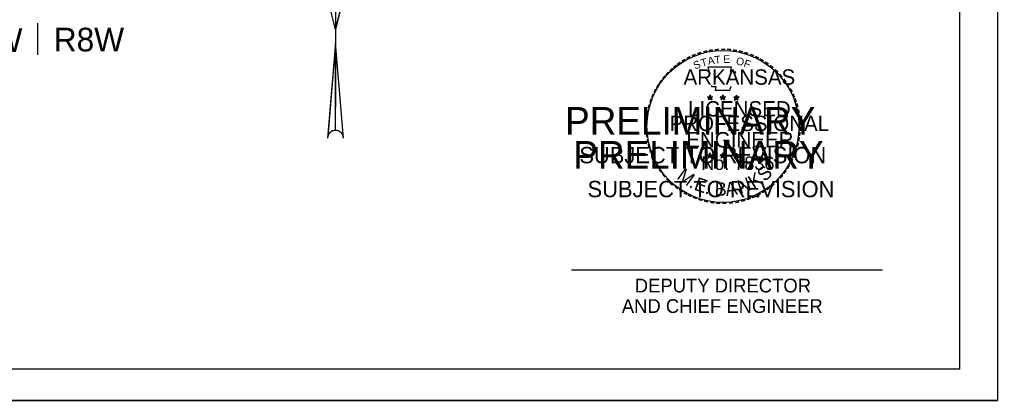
# Model space of a CAD drawing. Extents: x 1367863 to 1368197, y 380048 to 380261.
# Drawn here: x 1368072.7 to 1368196.7, y 380048.1 to 380096.4 of the extents above; entities that cross this region are included whole.
import ezdxf

# ---------------------------------------------------------------- set-up
doc = ezdxf.new("R2010")
doc.units = 0
for name, color, linetype in [('R_Border', 7, 'Continuous'), ('R_Border PE', 7, 'Continuous'), ('R_Border Prem', 7, 'Continuous'), ('R_Draft', 7, 'Continuous'), ('R_No Plot', 7, 'Continuous')]:
    doc.layers.add(name, color=color, linetype=linetype)

msp = doc.modelspace()

# ---------------------------------------------------------------- linework, layer by layer
at = {"layer": 'R_Border'}
for p, q in [((1368191.97, 380052.08), (1368191.97, 380257.54)), ((1368075.06, 380091.94), (1368075.06, 380095.94)), ((1368191.97, 380052.08), (1367875.8, 380052.08))]:
    msp.add_line(p, q, dxfattribs=at)
at = {"layer": 'R_Border PE'}
for p, q in [((1368160.28, 380086.85), (1368160.24, 380086.6)), ((1368160.28, 380086.49), (1368160.28, 380086.85)), ((1368160.28, 380086.85), (1368160.33, 380086.61)), ((1368161.91, 380086.85), (1368161.87, 380086.6)), ((1368161.91, 380086.49), (1368161.91, 380086.85)), ((1368161.91, 380086.85), (1368161.95, 380086.61)), ((1368163.62, 380086.83), (1368163.58, 380086.59)), ((1368163.62, 380086.48), (1368163.62, 380086.83)), ((1368163.62, 380086.83), (1368163.66, 380086.59)), ((1368159.94, 380086.6), (1368160.28, 380086.49)), ((1368159.94, 380086.6), (1368160.19, 380086.56)), ((1368159.94, 380086.6), (1368160.17, 380086.48)), ((1368160.07, 380086.2), (1368160.28, 380086.49)), ((1368160.07, 380086.2), (1368160.19, 380086.44)), ((1368160.07, 380086.2), (1368160.27, 380086.41)), ((1368160.49, 380086.2), (1368160.27, 380086.41)), ((1368160.61, 380086.6), (1368160.28, 380086.49)), ((1368160.49, 380086.2), (1368160.28, 380086.49)), ((1368160.61, 380086.6), (1368160.34, 380086.55)), ((1368160.49, 380086.2), (1368160.35, 380086.48)), ((1368160.61, 380086.6), (1368160.42, 380086.5)), ((1368161.57, 380086.6), (1368161.91, 380086.49)), ((1368161.57, 380086.6), (1368161.81, 380086.56)), ((1368161.57, 380086.6), (1368161.79, 380086.48)), ((1368161.69, 380086.2), (1368161.91, 380086.49)), ((1368161.69, 380086.2), (1368161.82, 380086.44)), ((1368161.69, 380086.2), (1368161.9, 380086.41)), ((1368162.11, 380086.2), (1368161.9, 380086.41)), ((1368162.24, 380086.6), (1368161.91, 380086.49)), ((1368162.11, 380086.2), (1368161.91, 380086.49)), ((1368162.24, 380086.6), (1368161.96, 380086.55)), ((1368162.11, 380086.2), (1368161.97, 380086.48)), ((1368162.24, 380086.6), (1368162.04, 380086.5)), ((1368163.28, 380086.59), (1368163.62, 380086.48)), ((1368163.28, 380086.59), (1368163.52, 380086.54)), ((1368163.28, 380086.59), (1368163.51, 380086.47)), ((1368163.4, 380086.19), (1368163.62, 380086.48)), ((1368163.4, 380086.19), (1368163.53, 380086.43)), ((1368163.4, 380086.19), (1368163.62, 380086.4)), ((1368163.96, 380086.59), (1368163.62, 380086.48)), ((1368163.82, 380086.19), (1368163.62, 380086.48)), ((1368163.82, 380086.19), (1368163.62, 380086.4)), ((1368163.96, 380086.59), (1368163.67, 380086.54)), ((1368163.82, 380086.19), (1368163.69, 380086.47)), ((1368163.96, 380086.59), (1368163.75, 380086.49)), ((1368159.93, 380079.24), (1368160.27, 380079.13)), ((1368159.93, 380079.24), (1368160.19, 380079.19)), ((1368159.93, 380079.24), (1368160.17, 380079.12)), ((1368160.27, 380079.48), (1368160.23, 380079.24)), ((1368160.27, 380079.13), (1368160.27, 380079.48)), ((1368160.27, 380079.48), (1368160.32, 380079.24)), ((1368160.61, 380079.24), (1368160.27, 380079.13)), ((1368160.61, 380079.24), (1368160.33, 380079.19)), ((1368160.61, 380079.24), (1368160.42, 380079.14)), ((1368161.56, 380079.24), (1368161.9, 380079.13)), ((1368161.56, 380079.24), (1368161.81, 380079.19)), ((1368161.56, 380079.24), (1368161.79, 380079.12)), ((1368161.9, 380079.48), (1368161.86, 380079.24)), ((1368161.9, 380079.13), (1368161.9, 380079.48)), ((1368161.9, 380079.48), (1368161.94, 380079.24)), ((1368162.24, 380079.24), (1368161.9, 380079.13)), ((1368162.24, 380079.24), (1368161.95, 380079.19)), ((1368162.24, 380079.24), (1368162.03, 380079.14)), ((1368163.28, 380079.23), (1368163.62, 380079.12)), ((1368163.28, 380079.23), (1368163.52, 380079.18)), ((1368163.28, 380079.23), (1368163.51, 380079.11)), ((1368163.62, 380079.47), (1368163.58, 380079.23)), ((1368163.62, 380079.12), (1368163.62, 380079.47)), ((1368163.62, 380079.47), (1368163.66, 380079.23)), ((1368163.96, 380079.23), (1368163.62, 380079.12)), ((1368163.96, 380079.23), (1368163.67, 380079.18)), ((1368163.96, 380079.23), (1368163.75, 380079.13)), ((1368160.07, 380078.84), (1368160.27, 380079.13)), ((1368160.07, 380078.84), (1368160.19, 380079.08)), ((1368160.07, 380078.84), (1368160.27, 380079.06)), ((1368160.49, 380078.84), (1368160.27, 380079.13)), ((1368160.49, 380078.84), (1368160.27, 380079.05)), ((1368160.49, 380078.84), (1368160.35, 380079.12)), ((1368161.69, 380078.84), (1368161.9, 380079.13)), ((1368161.69, 380078.84), (1368161.81, 380079.08)), ((1368161.69, 380078.84), (1368161.9, 380079.06)), ((1368162.1, 380078.84), (1368161.9, 380079.13)), ((1368162.1, 380078.84), (1368161.9, 380079.05)), ((1368162.1, 380078.84), (1368161.97, 380079.12)), ((1368163.4, 380078.83), (1368163.62, 380079.12)), ((1368163.4, 380078.83), (1368163.53, 380079.07)), ((1368163.4, 380078.83), (1368163.62, 380079.05)), ((1368163.82, 380078.83), (1368163.62, 380079.12)), ((1368163.82, 380078.83), (1368163.62, 380079.04)), ((1368163.82, 380078.83), (1368163.68, 380079.11)), ((1368142.71, 380064.66), (1368182.14, 380064.66))]:
    msp.add_line(p, q, dxfattribs=at)
for points in [[(1368159.98, 380090.37), (1368160.24, 380089.56)], [(1368163.39, 380089.48), (1368163.53, 380089.75), (1368162.87, 380089.73), (1368163, 380090.37), (1368159.98, 380090.37)], [(1368160.46, 380088.02), (1368160.46, 380087.93), (1368161, 380087.91), (1368160.95, 380087.45), (1368162.77, 380087.45), (1368162.97, 380087.97)], [(1368160.28, 380086.85), (1368160.49, 380086.2), (1368159.94, 380086.6), (1368160.61, 380086.6), (1368160.07, 380086.2), (1368160.28, 380086.85)], [(1368161.91, 380086.85), (1368162.11, 380086.2), (1368161.57, 380086.6), (1368162.24, 380086.6), (1368161.69, 380086.2), (1368161.91, 380086.85)], [(1368163.62, 380086.83), (1368163.82, 380086.19), (1368163.28, 380086.59), (1368163.96, 380086.59), (1368163.4, 380086.19), (1368163.62, 380086.83)], [(1368160.27, 380079.48), (1368160.49, 380078.84), (1368159.93, 380079.24), (1368160.61, 380079.24), (1368160.07, 380078.84), (1368160.27, 380079.48)], [(1368161.9, 380079.48), (1368162.1, 380078.84), (1368161.56, 380079.24), (1368162.24, 380079.24), (1368161.69, 380078.84), (1368161.9, 380079.48)], [(1368163.62, 380079.47), (1368163.82, 380078.83), (1368163.28, 380079.23), (1368163.96, 380079.23), (1368163.4, 380078.83), (1368163.62, 380079.47)]]:
    msp.add_lwpolyline(points, dxfattribs=at)
for centre, radius in [((1368161.92, 380082.85), 9.64), ((1368160.27, 380086.48), 0.167), ((1368160.27, 380086.48), 0.141), ((1368160.27, 380086.48), 0.113), ((1368160.27, 380086.48), 0.0963), ((1368160.27, 380086.48), 0.0726), ((1368160.27, 380086.48), 0.0482), ((1368160.27, 380086.48), 0.0288), ((1368161.89, 380086.48), 0.167), ((1368161.89, 380086.48), 0.141), ((1368161.89, 380086.48), 0.113), ((1368161.89, 380086.48), 0.0963), ((1368161.89, 380086.48), 0.0726), ((1368161.89, 380086.48), 0.0482), ((1368161.89, 380086.48), 0.0288), ((1368163.61, 380086.47), 0.167), ((1368163.61, 380086.47), 0.141), ((1368163.61, 380086.47), 0.113), ((1368163.61, 380086.47), 0.0963), ((1368163.61, 380086.47), 0.0726), ((1368163.61, 380086.47), 0.0482), ((1368163.61, 380086.47), 0.0288), ((1368160.26, 380079.12), 0.167), ((1368160.26, 380079.12), 0.141), ((1368160.26, 380079.12), 0.113), ((1368161.89, 380079.12), 0.167), ((1368161.89, 380079.12), 0.141), ((1368161.89, 380079.12), 0.113), ((1368163.6, 380079.11), 0.167), ((1368163.6, 380079.11), 0.141), ((1368163.6, 380079.11), 0.113), ((1368160.26, 380079.12), 0.0963), ((1368160.26, 380079.12), 0.0726), ((1368160.26, 380079.12), 0.0482), ((1368160.26, 380079.12), 0.0288), ((1368161.89, 380079.12), 0.0963), ((1368161.89, 380079.12), 0.0726), ((1368161.89, 380079.12), 0.0482), ((1368161.89, 380079.12), 0.0288), ((1368163.6, 380079.11), 0.0963), ((1368163.6, 380079.11), 0.0726), ((1368163.6, 380079.11), 0.0482), ((1368163.6, 380079.11), 0.0288)]:
    msp.add_circle(centre, radius, dxfattribs=at)
at = {"layer": 'R_Draft'}
for p, q in [((1368112.79, 380095.12), (1368113.57, 380098.19)), ((1368112.79, 380098.12), (1368112.79, 380085.31)), ((1368112.79, 380098.12), (1368112.79, 380095.12)), ((1368112.79, 380093.45), (1368111.8, 380081.51)), ((1368112.79, 380082.35), (1368112.79, 380093.45))]:
    msp.add_line(p, q, dxfattribs=at)
for points in [[(1368113.57, 380098.19), (1368112.79, 380095.12), (1368112.01, 380098.19)], [(1368113.79, 380081.35), (1368112.79, 380093.45), (1368111.79, 380081.35)]]:
    msp.add_lwpolyline(points, dxfattribs=at)
for start, end in [(0, 180), (90, 170.5511)]:
    msp.add_arc((1368112.79, 380081.35), 1, start, end, dxfattribs=at)
at = {"layer": 'R_No Plot'}
for p, q in [((1367863.39, 380048.1), (1368196.72, 380048.1)), ((1367863.4, 380048.11), (1368196.72, 380048.11))]:
    msp.add_line(p, q, dxfattribs=at)
msp.add_lwpolyline([(1367863.39, 380261.43), (1368196.72, 380261.43), (1368196.72, 380048.1), (1367863.39, 380048.1)], close=True, dxfattribs=at)

# ---------------------------------------------------------------- texts
at = {"layer": 'R_Border PE'}
for s, height, rotation, p in [('-', 1.56, 28.7918, (1368157.53, 380090.9)), ('-', 1.56, 24.3072, (1368158.14, 380091.21)), ('-', 1.56, 19.1761, (1368158.77, 380091.47)), ('-', 1.56, 13.6301, (1368159.5, 380091.7)), ('A', 0.972, 11.2132, (1368160.07, 380090.62)), ('-', 1.56, 10.2193, (1368160.15, 380091.86)), ('T', 0.972, 6.0228, (1368160.89, 380090.79)), ('-', 1.56, 5.8968, (1368160.86, 380091.96)), ('-', 1.56, 0.1862, (1368161.61, 380092.03)), ('E', 0.972, 0.8323, (1368161.97, 380090.9)), ('-', 1.56, 357.743, (1368162.31, 380092.02)), ('-', 1.56, 352.1617, (1368163.03, 380091.96)), ('-', 1.56, 347.2049, (1368163.73, 380091.86)), ('-', 1.56, 342.3362, (1368164.36, 380091.7)), ('-', 1.56, 337.8551, (1368165.06, 380091.49)), ('-', 1.56, 334.1211, (1368165.68, 380091.23)), ('-', 1.56, 38.9507, (1368155.93, 380089.79)), ('-', 1.56, 36.2317, (1368156.38, 380090.16)), ('-', 1.56, 34.0636, (1368156.95, 380090.54)), ('S', 0.972, 21.594, (1368158.38, 380090.06)), ('T', 0.972, 16.4036, (1368159.27, 380090.38)), ('O', 0.972, 350.4515, (1368163.53, 380090.69)), ('F', 0.972, 340.0707, (1368164.46, 380090.47)), ('-', 1.56, 329.6409, (1368166.24, 380090.95)), ('-', 1.56, 325.8627, (1368166.86, 380090.6)), ('-', 1.56, 320.5297, (1368167.46, 380090.19)), ('-', 1.56, 50.6142, (1368154.67, 380088.45)), ('-', 1.56, 48.4231, (1368155.07, 380088.91)), ('-', 1.56, 42.9622, (1368155.51, 380089.38)), ('ARKANSAS', 1.944, 360, (1368156.92, 380088.14)), ('-', 1.56, 315.5786, (1368168.04, 380089.71)), ('-', 1.56, 309.8797, (1368168.59, 380089.17)), ('-', 1.56, 58.0706, (1368153.96, 380087.38)), ('-', 1.56, 54.2325, (1368154.28, 380087.89)), ('-', 1.56, 306.6522, (1368169.11, 380088.59)), ('-', 1.36, 303.6753, (1368169.57, 380088.04)), ('-', 1.56, 67.7743, (1368153.4, 380086.19)), ('-', 1.56, 62.8713, (1368153.65, 380086.78)), ('-', 1.56, 299.6684, (1368169.89, 380087.44)), ('-', 1.56, 294.6628, (1368170.21, 380086.85)), ('-', 1.56, 75.461, (1368153, 380084.88)), ('-', 1.56, 72.3945, (1368153.2, 380085.58)), ('LICENSED', 1.944, 360, (1368157.5, 380084.11)), ('-', 1.56, 290.5728, (1368170.45, 380086.3)), ('-', 1.56, 285.1233, (1368170.68, 380085.73)), ('-', 1.56, 81.2013, (1368152.88, 380084.19)), ('PROFESSIONAL', 1.9439, 360, (1368155.15, 380082.26)), ('-', 1.56, 280.5493, (1368170.88, 380085)), ('-', 1.56, 276.5962, (1368171.03, 380084.27)), ('-', 1.56, 89.0622, (1368152.78, 380082.84)), ('-', 1.56, 85.1863, (1368152.8, 380083.52)), ('-', 1.56, 274.3301, (1368171.09, 380083.56)), ('-', 1.56, 94.1959, (1368152.81, 380082.13)), ('-', 1.56, 98.9479, (1368152.88, 380081.49)), ('ENGINEER', 1.944, 360, (1368157.27, 380080.19)), ('-', 1.56, 263.5172, (1368171.1, 380082.3)), ('-', 1.56, 269.9407, (1368171.12, 380082.94)), ('-', 1.56, 101.7149, (1368153.01, 380080.77)), ('-', 1.56, 105.4578, (1368153.17, 380080.19)), ('-', 1.56, 255.7626, (1368170.93, 380081)), ('-', 1.56, 260.9953, (1368171.03, 380081.66)), ('-', 1.56, 109.0874, (1368153.37, 380079.58)), ('-', 1.56, 114.0643, (1368153.62, 380079)), ('-', 1.56, 247.8887, (1368170.54, 380079.65)), ('-', 1.56, 252.8681, (1368170.75, 380080.3)), ('-', 1.56, 115.7289, (1368153.92, 380078.4)), ('-', 1.56, 120.4471, (1368154.27, 380077.83)), ('No. 7836', 1.708, 360, (1368159.17, 380077.33)), ('-', 1.56, 244.6197, (1368170.28, 380079.04)), ('-', 1.56, 125.8934, (1368154.65, 380077.29)), ('-', 1.56, 130.7181, (1368155.11, 380076.74)), ('M', 1.71, 323.9056, (1368155.97, 380076.31)), ('K', 1.71, 32.2382, (1368165.8, 380074.9)), ('S', 1.71, 42.9205, (1368167.21, 380075.76)), ('-', 1.56, 233.8452, (1368169.51, 380077.68)), ('-', 1.56, 239.0712, (1368169.9, 380078.31)), ('-', 1.56, 134.2238, (1368155.61, 380076.22)), ('-', 1.56, 138.9338, (1368156.12, 380075.77)), ('E', 1.71, 340.8881, (1368158.14, 380074.85)), ('B', 1.71, 359.3149, (1368160.86, 380074.07)), ('A', 1.71, 8.7702, (1368162.32, 380074.01)), ('N', 1.71, 20.5042, (1368164.11, 380074.28)), ('-', 1.56, 221.0851, (1368168.12, 380076.08)), ('-', 1.56, 225.7653, (1368168.62, 380076.58)), ('-', 1.56, 231.2538, (1368169.09, 380077.12)), ('-', 1.56, 144.6463, (1368156.66, 380075.37)), ('-', 1.56, 148.0898, (1368157.2, 380075.01)), ('-', 1.56, 151.5704, (1368157.76, 380074.69)), ('.', 1.71, 336.3407, (1368157.52, 380075.18)), ('.', 1.71, 350.694, (1368159.56, 380074.33)), ('-', 1.56, 207.3568, (1368166.52, 380074.91)), ('-', 1.56, 212.2491, (1368167.07, 380075.25)), ('-', 1.56, 215.7363, (1368167.58, 380075.63)), ('-', 1.56, 154.6002, (1368158.28, 380074.46)), ('-', 1.56, 158.5612, (1368158.88, 380074.21)), ('-', 1.56, 162.7983, (1368159.55, 380074)), ('-', 1.56, 167.5555, (1368160.24, 380073.85)), ('-', 1.56, 173.1155, (1368160.99, 380073.74)), ('-', 1.56, 176.5183, (1368161.7, 380073.68)), ('-', 1.56, 181.5918, (1368162.43, 380073.7)), ('-', 1.56, 185.8167, (1368163.23, 380073.78)), ('-', 1.56, 191.2858, (1368163.95, 380073.9)), ('-', 1.56, 195.4743, (1368164.66, 380074.1)), ('-', 1.56, 200.7184, (1368165.32, 380074.33)), ('-', 1.56, 204.2516, (1368165.92, 380074.59)), ('DEPUTY DIRECTOR', 1.7495, 360, (1368150.73, 380061.79)), ('AND CHIEF ENGINEER', 1.7495, 360, (1368149.09, 380059.19))]:
    msp.add_text(s, height=height, rotation=rotation, dxfattribs=at).set_placement(p)
at = {"layer": 'R_Border Prem'}
for s, height, p in [('PRELIMINARY', 3.4999, (1368141.9, 380081.8)), ('SUBJECT TO REVISION', 2.075, (1368143.71, 380078.17))]:
    msp.add_text(s, height=height, rotation=360, dxfattribs=at).set_placement(p)
for s, height, p in [('PRELIMINARY', 3.5, (1368142.94, 380077.49)), ('SUBJECT TO REVISION', 2.0751, (1368144.75, 380073.87))]:
    msp.add_text(s, height=height, dxfattribs=at).set_placement(p)
at = {"layer": 'R_Draft'}
for s, p in [('R8W', (1368077.07, 380092.36)), ('R9W', (1368064.18, 380092.29))]:
    msp.add_text(s, height=3, dxfattribs=at).set_placement(p)

doc.saveas('drawing.dxf')
